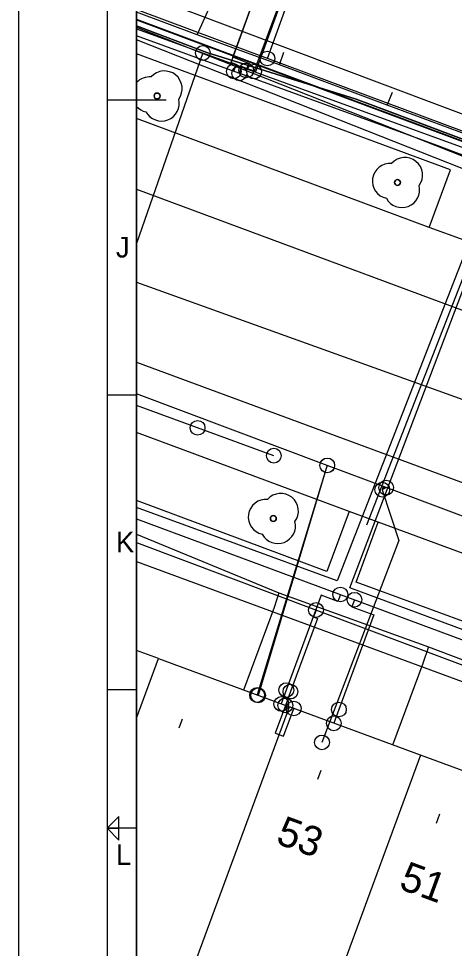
# Model space of a CAD drawing. Extents: x 192672 to 192910, y 446344 to 446512.
# Drawn here: x 192671.74 to 192686.52, y 446398.88 to 446430.41 of the extents above; entities that cross this region are included whole.
import ezdxf

# ---------------------------------------------------------------- set-up
doc = ezdxf.new("R2010")
doc.units = 0
for name, color, linetype in [('1010 viewport', 7, 'Continuous'), ('B-OI-KL-()_PUNTVANLEVERING_WATER-S', 7, 'Continuous'), ('B-OI-KL-BUISLEIDING_OLIEGASCHEMICALIEN_GASLAGEDRUK-G', 7, 'Continuous'), ('B-OI-KL-DATA-G', 7, 'Continuous'), ('B-OI-KL-DATA_GTWP-S', 7, 'Continuous'), ('B-OI-KL-DATA_KABELBED-G', 7, 'Continuous'), ('B-OI-KL-DATA_MOF-S', 7, 'Continuous'), ('B-OI-KL-ET_LS-G', 7, 'Continuous'), ('B-OI-KL-ET_LS_DELIVERYPOINT-S', 7, 'Continuous'), ('B-OI-KL-ET_LS_MANTELBUIS-G', 7, 'Continuous'), ('B-OI-KL-ET_LS_MOF-S', 7, 'Continuous'), ('B-OI-KL-ET_MS-G', 7, 'Continuous'), ('B-OI-KL-GAS_LD_AFTAKZADEL-S', 7, 'Continuous'), ('B-OI-KL-GAS_LD_DELIVERYPOINT-S', 7, 'Continuous'), ('B-OI-KL-GAS_LD_OVERGANGSSTUK-S', 7, 'Continuous'), ('B-OI-KL-WATER-G', 7, 'Continuous'), ('B-OI-RI-RIOOLVRIJVERVAL-G', 7, 'Continuous'), ('boom', 7, 'Continuous'), ('Default', 7, 'Continuous'), ('huisnummerreeks BGT', 7, 'Continuous'), ('kant open verharding', 7, 'Continuous'), ('kant verharding', 7, 'Continuous'), ('pand op maaiveld vlak', 7, 'Continuous'), ('verkeerseiland - berm', 7, 'Continuous'), ('X-XX-AL-TEKENBLAD-S', 7, 'Continuous')]:
    doc.layers.add(name, color=color, linetype=linetype)

# ---------------------------------------------------------------- blocks, each defined once
blk = doc.blocks.new('B-OI-KL-GAS_LD_AFTAKZADEL-S')
at = {"layer": 'Default'}
blk.add_circle((0, 0), 0.25, dxfattribs=at)
blk = doc.blocks.new('B-OI-KL-GAS_LD_DELIVERYPOINT-S')
at = {"layer": 'Default'}
blk.add_circle((0, 0), 0.25, dxfattribs=at)
blk = doc.blocks.new('B-OI-KL-GAS_LD_OVERGANGSSTUK-S')
at = {"layer": 'Default'}
blk.add_circle((0, 0), 0.25, dxfattribs=at)
blk = doc.blocks.new('B-OI-KL-ET_LS_DELIVERYPOINT-S')
at = {"layer": 'Default'}
blk.add_circle((0, 0), 0.25, dxfattribs=at)
blk = doc.blocks.new('B-OI-KL-ET_LS_MOF-S')
at = {"layer": 'Default'}
blk.add_circle((0, 0), 0.25, dxfattribs=at)
blk = doc.blocks.new('B-OI-KL-()_PUNTVANLEVERING_WATER-S')
at = {"layer": 'Default'}
blk.add_circle((0, 0), 0.25, dxfattribs=at)
blk = doc.blocks.new('B-OI-KL-DATA_GTWP-S')
at = {"layer": 'Default'}
blk.add_circle((0, 0), 0.25, dxfattribs=at)
blk = doc.blocks.new('B-OI-KL-DATA_MOF-S')
at = {"layer": 'Default'}
blk.add_circle((0, 0), 0.25, dxfattribs=at)

msp = doc.modelspace()

# ---------------------------------------------------------------- linework, layer by layer
at = {"layer": '1010 viewport'}
msp.add_lwpolyline([(192675.743, 446509.756), (192860.643, 446509.756), (192860.643, 446345.556), (192675.743, 446345.556)], close=True, dxfattribs=at)
at = {"layer": 'B-OI-KL-BUISLEIDING_OLIEGASCHEMICALIEN_GASLAGEDRUK-G'}
msp.add_line((192675.743, 446413.446), (192709.208, 446401.012), dxfattribs=at)
for points in [[(192679.039, 446428.617), (192679.125, 446428.851), (192678.947, 446428.916), (192680.197, 446432.358)], [(192679.227, 446428.548), (192679.313, 446428.783), (192679.782, 446428.611), (192681.047, 446432.092)], [(192739.245, 446406.116), (192738.416, 446406.482), (192717.09, 446414.534), (192687.866, 446425.386), (192686.502, 446425.892), (192685.933, 446426.1), (192675.743, 446429.821)], [(192682.651, 446410.88), (192682.564, 446410.646), (192682.005, 446410.854), (192680.82, 446407.641)], [(192683.13, 446410.702), (192683.043, 446410.468), (192683.787, 446410.191), (192682.604, 446406.982)], [(192680.82, 446407.641), (192680.647, 446407.172)], [(192682.604, 446406.982), (192682.431, 446406.514)]]:
    msp.add_lwpolyline(points, dxfattribs=at)
at = {"layer": 'B-OI-KL-DATA-G'}
for p, q in [((192677.798, 446429.859), (192675.743, 446430.624)), ((192675.743, 446412.921), (192680.561, 446410.942))]:
    msp.add_line(p, q, dxfattribs=at)
for points in [[(192768.74, 446486.807), (192749.794, 446435.599), (192742.072, 446415.039), (192739.06, 446406.841), (192720.2, 446413.77), (192719.012, 446414.118), (192696.077, 446422.823), (192683.193, 446427.673), (192678.122, 446429.261), (192675.743, 446430.156)], [(192675.743, 446430.36), (192720.2, 446413.771), (192739.906, 446406.53), (192752.421, 446411.058), (192770.152, 446404.44), (192773.577, 446403.064), (192825.629, 446383.71), (192826.856, 446388.539), (192834.171, 446407.983), (192839.017, 446421.742), (192838.042, 446426.7), (192842.865, 446440.095), (192846.683, 446450.008), (192848.26, 446453.903), (192848.365, 446454.374), (192848.254, 446454.945), (192844.011, 446462.681), (192860.643, 446470.952)], [(192745.236, 446436.264), (192745.276, 446436.371), (192749.491, 446434.791), (192742.072, 446415.039), (192739.06, 446406.841), (192720.2, 446413.77), (192719.012, 446414.118), (192696.077, 446422.823), (192683.193, 446427.673), (192678.122, 446429.261), (192675.743, 446430.156)], [(192677.798, 446429.859), (192679.245, 446433.081), (192679.313, 446433.219)], [(192737.667, 446407.73), (192737.22, 446407.782), (192736.663, 446407.985), (192736.03, 446408.286), (192735.626, 446408.365), (192729.863, 446410.472), (192728.465, 446411.08), (192721.146, 446413.773), (192716.247, 446415.615), (192710.715, 446417.628), (192706.774, 446419.101), (192701.477, 446421.077), (192698.04, 446422.325), (192693.262, 446424.115), (192691.867, 446424.65), (192684.239, 446427.468), (192680.591, 446428.834), (192677.798, 446429.859), (192675.743, 446430.624)], [(192675.743, 446430.156), (192678.122, 446429.261), (192683.193, 446427.673), (192696.077, 446422.823), (192719.012, 446414.118), (192720.2, 446413.77), (192739.06, 446406.841), (192738.917, 446406.249), (192738.75, 446405.758), (192738.438, 446405.088), (192738.002, 446404.406), (192737.543, 446403.858), (192737.067, 446403.408), (192736.56, 446403.025), (192736.06, 446402.723), (192733.684, 446396.245), (192734.518, 446394.712), (192730.316, 446383.423), (192727.316, 446375.697), (192722.899, 446364.033), (192722.458, 446362.715), (192718.077, 446351.086), (192716.68, 446347.404), (192715.968, 446345.556)], [(192675.743, 446430.156), (192678.122, 446429.261), (192683.193, 446427.673), (192696.077, 446422.823), (192719.012, 446414.118), (192720.2, 446413.77), (192739.06, 446406.841), (192738.917, 446406.249), (192738.75, 446405.758), (192738.438, 446405.088), (192738.002, 446404.406), (192737.543, 446403.858), (192737.067, 446403.408), (192736.56, 446403.025), (192736.06, 446402.723), (192733.684, 446396.245), (192734.518, 446394.712), (192730.316, 446383.423), (192727.316, 446375.697), (192722.899, 446364.033), (192722.458, 446362.715), (192718.077, 446351.086), (192716.68, 446347.404), (192715.968, 446345.556)], [(192675.743, 446430.156), (192678.122, 446429.261), (192683.193, 446427.673), (192696.077, 446422.823), (192719.012, 446414.118), (192720.2, 446413.77), (192739.06, 446406.841), (192738.917, 446406.249), (192738.75, 446405.758), (192738.438, 446405.088), (192738.002, 446404.406), (192737.543, 446403.858), (192737.067, 446403.408), (192736.56, 446403.025), (192736.06, 446402.723), (192733.684, 446396.245), (192734.518, 446394.712), (192730.316, 446383.423), (192727.316, 446375.697), (192722.899, 446364.033), (192722.458, 446362.715), (192718.077, 446351.086), (192716.68, 446347.404), (192715.968, 446345.556)], [(192675.743, 446430.156), (192678.122, 446429.261), (192683.193, 446427.673), (192696.077, 446422.823), (192719.012, 446414.118), (192720.2, 446413.77), (192739.06, 446406.841), (192738.917, 446406.249), (192738.75, 446405.758), (192738.438, 446405.088), (192738.002, 446404.406), (192737.543, 446403.858), (192737.067, 446403.408), (192736.56, 446403.025), (192736.06, 446402.723), (192733.684, 446396.245), (192734.518, 446394.712), (192730.316, 446383.423), (192727.316, 446375.697), (192722.899, 446364.033), (192722.458, 446362.715), (192718.077, 446351.086), (192716.68, 446347.404), (192715.968, 446345.556)], [(192675.743, 446430.156), (192678.122, 446429.261), (192683.193, 446427.673), (192696.077, 446422.823), (192719.012, 446414.118), (192720.2, 446413.77), (192739.06, 446406.841), (192738.917, 446406.249), (192738.75, 446405.758), (192738.438, 446405.088), (192738.002, 446404.406), (192737.543, 446403.858), (192737.067, 446403.408), (192736.56, 446403.025), (192736.06, 446402.723), (192733.684, 446396.245), (192734.518, 446394.712), (192730.316, 446383.423), (192727.316, 446375.697), (192722.899, 446364.033), (192722.458, 446362.715), (192718.077, 446351.086), (192716.68, 446347.404), (192715.968, 446345.556)], [(192675.743, 446430.156), (192678.122, 446429.261), (192683.193, 446427.673), (192696.077, 446422.823), (192719.012, 446414.118), (192720.2, 446413.77), (192739.06, 446406.841), (192738.917, 446406.249), (192738.75, 446405.758), (192738.438, 446405.088), (192738.002, 446404.406), (192737.543, 446403.858), (192737.067, 446403.408), (192736.56, 446403.025), (192736.06, 446402.723), (192733.684, 446396.245), (192734.518, 446394.712), (192730.316, 446383.423), (192727.316, 446375.697), (192722.899, 446364.033), (192722.458, 446362.715), (192718.077, 446351.086), (192716.68, 446347.404), (192715.968, 446345.556)], [(192680.591, 446428.834), (192677.798, 446429.859)], [(192680.591, 446428.834), (192680.74, 446429.266)], [(192684.239, 446427.468), (192680.591, 446428.834)], [(192684.239, 446427.468), (192684.417, 446427.914)], [(192691.867, 446424.65), (192684.239, 446427.468)], [(192680.561, 446410.942), (192680.403, 446410.438), (192679.371, 446407.642)], [(192680.561, 446410.942), (192685.635, 446409.106)], [(192685.635, 446409.106), (192685.444, 446408.54), (192684.425, 446405.778)], [(192685.635, 446409.106), (192689.311, 446407.716)], [(192677.182, 446406.357), (192677.295, 446406.662)], [(192681.886, 446404.618), (192682.001, 446404.929)], [(192685.908, 446403.131), (192686.025, 446403.448)]]:
    msp.add_lwpolyline(points, dxfattribs=at)
at = {"layer": 'B-OI-KL-DATA_KABELBED-G'}
msp.add_line((192677.812, 446416.531), (192675.743, 446417.293), dxfattribs=at)
for points in [[(192680.18, 446429.054), (192681.402, 446432.441)], [(192738.388, 446407.619), (192734.688, 446408.978), (192724.883, 446412.582), (192723.845, 446412.963), (192720.372, 446414.239), (192719.183, 446414.479), (192716.646, 446415.427), (192714.21, 446416.337), (192707.529, 446418.834), (192703.97, 446420.164), (192697.852, 446422.451), (192697.2, 446422.694), (192695.696, 446423.256), (192692.683, 446424.382), (192687.423, 446426.348), (192680.18, 446429.054), (192675.857, 446430.67), (192675.743, 446430.712)], [(192684.245, 446427.277), (192683.193, 446427.673), (192678.122, 446429.261), (192675.743, 446430.156)], [(192689.435, 446425.323), (192684.245, 446427.277)], [(192733.82, 446395.718), (192726.444, 446398.553), (192717.381, 446402.036), (192715.981, 446402.574), (192711.535, 446404.244), (192702.923, 446407.477), (192692.564, 446411.367), (192684.205, 446414.506), (192682.207, 446415.256), (192682.206, 446415.257), (192675.743, 446417.684)], [(192680.397, 446415.587), (192677.812, 446416.531)], [(192682.207, 446415.256), (192682.174, 446415.15), (192679.828, 446407.474)], [(192682.206, 446415.257), (192682.174, 446415.15), (192679.865, 446407.461)], [(192684.072, 446414.435), (192684.631, 446412.712), (192682.029, 446405.867)], [(192684.205, 446414.506), (192684.092, 446414.508), (192684.072, 446414.435)], [(192684.205, 446414.506), (192684.072, 446414.435)], [(192677.182, 446406.357), (192677.295, 446406.662)], [(192681.886, 446404.618), (192682.001, 446404.929)], [(192685.908, 446403.131), (192686.025, 446403.448)]]:
    msp.add_lwpolyline(points, dxfattribs=at)
at = {"layer": 'B-OI-KL-ET_LS-G'}
for points in [[(192679.46, 446428.648), (192679.552, 446428.88), (192679.002, 446429.098), (192680.022, 446431.889)], [(192675.743, 446430.115), (192687.837, 446425.34), (192737.952, 446406.43)], [(192751.683, 446410.693), (192751.552, 446410.731), (192751.472, 446410.738), (192751.395, 446410.716), (192751.332, 446410.668), (192751.29, 446410.599), (192748.269, 446402.545), (192740.519, 446405.455), (192737.866, 446406.039), (192687.696, 446424.966), (192675.743, 446429.685)], [(192687.898, 446423.091), (192687.234, 446423.375), (192682.544, 446411.341), (192675.743, 446413.827)], [(192705.001, 446404.897), (192704.48, 446404.329), (192704.196, 446403.239), (192682.97, 446411.104), (192687.329, 446422.57), (192687.898, 446423.091)], [(192675.743, 446412.643), (192733.67, 446390.862), (192732.765, 446387.575)], [(192681.826, 446410.355), (192681.738, 446410.121), (192681.875, 446410.07), (192680.96, 446407.589)], [(192680.96, 446407.589), (192680.787, 446407.12)], [(192680.787, 446407.12), (192680.441, 446406.182), (192680.723, 446406.078), (192681.069, 446407.016)]]:
    msp.add_lwpolyline(points, dxfattribs=at)
at = {"layer": 'B-OI-KL-ET_LS_MANTELBUIS-G'}
msp.add_lwpolyline([(192687.234, 446422.712), (192683.539, 446413.236)], dxfattribs=at)
at = {"layer": 'B-OI-KL-ET_MS-G'}
msp.add_lwpolyline([(192675.743, 446430.392), (192719.08, 446414.198), (192720.2, 446413.771), (192739.907, 446406.53), (192740.419, 446406.767), (192749.859, 446410.199), (192752.421, 446411.058), (192770.152, 446404.44), (192774.571, 446402.692), (192787.766, 446397.768), (192806.764, 446390.772), (192825.096, 446383.91)], dxfattribs=at)
at = {"layer": 'B-OI-KL-WATER-G'}
for p, q in [((192675.743, 446430.057), (192738.889, 446407.111)), ((192677.989, 446429.241), (192675.743, 446422.779))]:
    msp.add_line(p, q, dxfattribs=at)
msp.add_lwpolyline([(192679.728, 446428.609), (192681.19, 446432.52)], dxfattribs=at)
at = {"layer": 'B-OI-RI-RIOOLVRIJVERVAL-G'}
msp.add_line((192675.743, 446421.466), (192692.66, 446415.38), dxfattribs=at)
at = {"layer": 'boom'}
msp.add_line((192675.743, 446428.235), (192675.743, 446427.429), dxfattribs=at)
for centre in [(192676.438, 446427.782), (192684.588, 446424.849), (192680.38, 446413.459)]:
    msp.add_circle(centre, 0.1, dxfattribs=at)
for centre, radius, start, end in [((192676.188, 446427.832), 0.6, 85.137, 137.8197), ((192676.688, 446428.032), 0.6, 323.5446, 138.4658), ((192676.438, 446427.782), 0.1, 0, 180), ((192676.438, 446427.782), 0.1, 180, 0), ((192676.588, 446427.532), 0.6, 208.5058, 13.8356), ((192676.188, 446427.832), 0.6, 222.1803, 257.7544), ((192684.838, 446425.099), 0.6, 323.5446, 138.4658), ((192684.338, 446424.899), 0.6, 85.137, 257.7544), ((192684.588, 446424.849), 0.1, 0, 180), ((192684.738, 446424.599), 0.6, 208.5058, 13.8356), ((192684.588, 446424.849), 0.1, 180, 0), ((192680.63, 446413.709), 0.6, 323.5446, 138.4658), ((192680.13, 446413.509), 0.6, 85.137, 257.7544), ((192680.53, 446413.209), 0.6, 208.5058, 13.8356), ((192680.38, 446413.459), 0.1, 0, 180), ((192680.38, 446413.459), 0.1, 180, 0)]:
    msp.add_arc(centre, radius, start, end, dxfattribs=at)
at = {"layer": 'kant open verharding'}
for points in [[(192675.743, 446431.332), (192697.987, 446422.959), (192719.324, 446415.141), (192720.614, 446414.897)], [(192675.743, 446411.995), (192713.029, 446398.263), (192714.204, 446397.83), (192714.097, 446397.514)]]:
    msp.add_lwpolyline(points, dxfattribs=at)
at = {"layer": 'kant verharding'}
for p, q in [((192675.743, 446424.623), (192733.082, 446403.313)), ((192686.85, 446422.89), (192685.668, 446423.329)), ((192675.743, 446418.762), (192731.114, 446398.266)), ((192683.929, 446413.333), (192682.95, 446413.694))]:
    msp.add_line(p, q, dxfattribs=at)
at = {"layer": 'pand op maaiveld vlak'}
for p, q in [((192676.487, 446408.706), (192675.743, 446408.98)), ((192675.743, 446406.689), (192676.487, 446408.706)), ((192676.487, 446408.706), (192680.928, 446407.068)), ((192676.789, 446395.847), (192680.928, 446407.068)), ((192685.368, 446405.43), (192680.928, 446407.068)), ((192685.368, 446405.43), (192681.229, 446394.209)), ((192689.808, 446403.792), (192685.368, 446405.43))]:
    msp.add_line(p, q, dxfattribs=at)
at = {"layer": 'verkeerseiland - berm'}
for p, q in [((192685.668, 446423.329), (192675.743, 446427.021)), ((192682.95, 446413.694), (192675.743, 446416.376)), ((192699.029, 446407.759), (192683.929, 446413.333))]:
    msp.add_line(p, q, dxfattribs=at)
for points in [[(192685.668, 446423.329), (192686.387, 446425.276), (192675.743, 446429.208)], [(192682.95, 446413.694), (192682.193, 446411.661), (192675.743, 446414.063)], [(192699.029, 446407.759), (192698.296, 446405.758), (192683.182, 446411.296), (192683.929, 446413.333)]]:
    msp.add_lwpolyline(points, dxfattribs=at)
at = {"layer": 'X-XX-AL-TEKENBLAD-S'}
for p, q in [((192671.743, 446511.756), (192671.743, 446343.556)), ((192674.743, 446510.756), (192674.743, 446344.556)), ((192674.743, 446417.656), (192675.743, 446417.656)), ((192674.743, 446407.656), (192675.743, 446407.656)), ((192675.143, 446402.956), (192674.743, 446402.956)), ((192674.743, 446402.956), (192675.143, 446402.956)), ((192675.743, 446402.956), (192674.743, 446402.956))]:
    msp.add_line(p, q, dxfattribs=at)
msp.add_lwpolyline([(192675.743, 446345.556), (192907.543, 446345.556), (192907.543, 446509.756), (192675.743, 446509.756)], close=True, dxfattribs=at)
for points in [[(192674.743, 446427.656), (192676.743, 446427.656)], [(192675.143, 446402.956), (192675.143, 446403.356), (192674.743, 446402.956)], [(192674.743, 446402.956), (192675.143, 446402.556), (192675.143, 446402.956)]]:
    msp.add_lwpolyline(points, dxfattribs=at)

# ---------------------------------------------------------------- block references
at = {"layer": 'B-OI-KL-()_PUNTVANLEVERING_WATER-S'}
for p in [(192677.989, 446429.241), (192679.728, 446428.609)]:
    msp.add_blockref('B-OI-KL-()_PUNTVANLEVERING_WATER-S', p, dxfattribs=at)
at = {"layer": 'B-OI-KL-DATA_GTWP-S'}
for p in [(192680.18, 446429.054), (192677.812, 446416.531), (192677.812, 446416.531), (192680.397, 446415.587), (192682.206, 446415.257), (192682.207, 446415.256), (192684.072, 446414.435), (192684.072, 446414.435), (192684.072, 446414.435), (192684.205, 446414.506), (192684.205, 446414.506), (192679.828, 446407.474), (192679.865, 446407.461), (192682.029, 446405.867)]:
    msp.add_blockref('B-OI-KL-DATA_GTWP-S', p, dxfattribs=at)
at = {"layer": 'B-OI-KL-DATA_MOF-S'}
for p in [(192680.18, 446429.054), (192677.812, 446416.531), (192682.206, 446415.257), (192682.207, 446415.256), (192684.072, 446414.435), (192684.072, 446414.435), (192684.205, 446414.506), (192684.205, 446414.506)]:
    msp.add_blockref('B-OI-KL-DATA_MOF-S', p, dxfattribs=at)
at = {"layer": 'B-OI-KL-ET_LS_DELIVERYPOINT-S'}
for p in [(192680.787, 446407.12), (192681.069, 446407.016)]:
    msp.add_blockref('B-OI-KL-ET_LS_DELIVERYPOINT-S', p, dxfattribs=at)
at = {"layer": 'B-OI-KL-ET_LS_MOF-S'}
for p in [(192679.46, 446428.648), (192681.826, 446410.355), (192680.96, 446407.589)]:
    msp.add_blockref('B-OI-KL-ET_LS_MOF-S', p, dxfattribs=at)
at = {"layer": 'B-OI-KL-GAS_LD_AFTAKZADEL-S'}
for p in [(192679.039, 446428.617), (192679.227, 446428.548), (192682.651, 446410.88), (192683.13, 446410.702)]:
    msp.add_blockref('B-OI-KL-GAS_LD_AFTAKZADEL-S', p, dxfattribs=at)
at = {"layer": 'B-OI-KL-GAS_LD_DELIVERYPOINT-S'}
for p in [(192680.647, 446407.172), (192682.431, 446406.514)]:
    msp.add_blockref('B-OI-KL-GAS_LD_DELIVERYPOINT-S', p, dxfattribs=at)
at = {"layer": 'B-OI-KL-GAS_LD_OVERGANGSSTUK-S'}
for p in [(192680.82, 446407.641), (192682.604, 446406.982)]:
    msp.add_blockref('B-OI-KL-GAS_LD_OVERGANGSSTUK-S', p, dxfattribs=at)

# ---------------------------------------------------------------- texts
at = {"layer": 'huisnummerreeks BGT'}
for s, p in [('53', (192680.423, 446402.458)), ('51', (192684.597, 446400.917))]:
    msp.add_text(s, height=1, rotation=339.8, dxfattribs=at).set_placement(p)
at = {"layer": 'X-XX-AL-TEKENBLAD-S'}
for s, p in [('J', (192675.043, 446422.306)), ('K', (192675.043, 446412.306)), ('L', (192675.043, 446401.706))]:
    msp.add_text(s, height=0.7, dxfattribs=at).set_placement(p)

doc.saveas('drawing.dxf')
